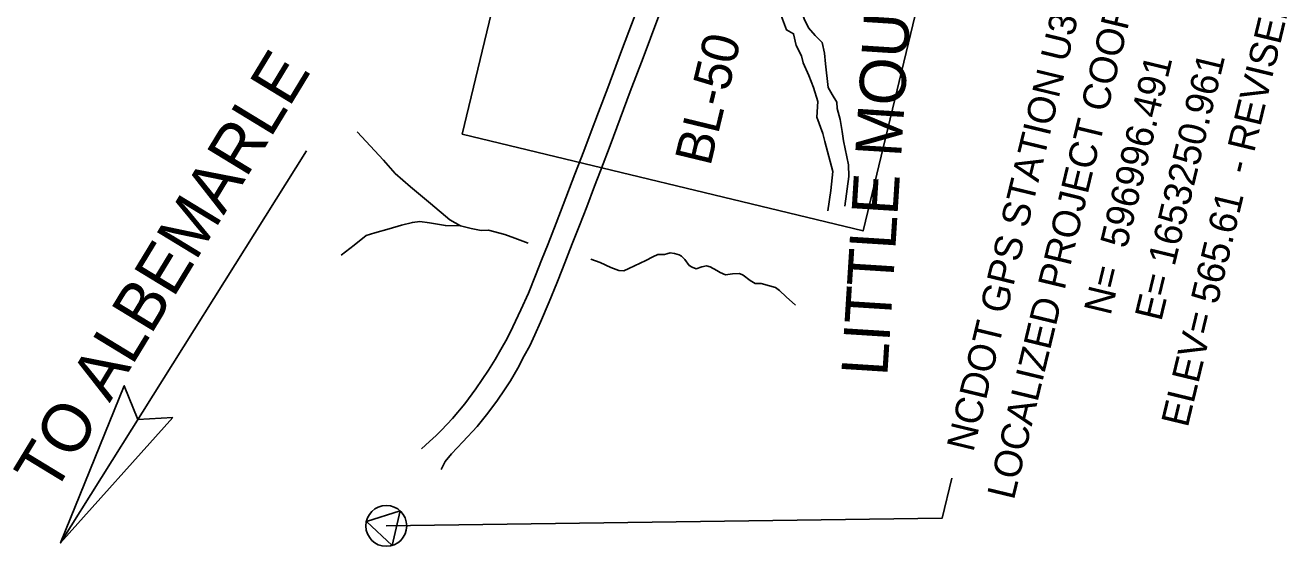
# Model space of a CAD drawing. Extents: x 1649669 to 1659218, y 588594 to 607900.
# Drawn here: x 1652859 to 1654231, y 596977 to 597539 of the extents above; entities that cross this region are included whole.
import ezdxf

# ---------------------------------------------------------------- set-up
doc = ezdxf.new("R2010")
doc.units = 0
for name, color, linetype in [('CTL NGS Horizontal CELL', 7, 'Continuous'), ('CTL NGS Horizontal Leader', 7, 'Continuous'), ('CTL NGS Horizontal Text', 7, 'Continuous'), ('CTL Supplemental Horizontal and Vertical Text', 7, 'Continuous'), ('Default', 7, 'Continuous'), ('Exist Hydro Jurisdictional Stream or Body of Water', 7, 'Continuous'), ('Exist Hydro Stream or Body of Water', 7, 'Continuous'), ('Exist Roads EOP', 7, 'Continuous'), ('Old_Level_20', 7, 'Continuous'), ('Prop Terminator CELL', 7, 'Continuous'), ('Sheet Cutting Line CELL', 7, 'Continuous'), ('Sheet Data Field CELL', 7, 'Continuous')]:
    doc.layers.add(name, color=color, linetype=linetype)

# ---------------------------------------------------------------- blocks, each defined once
blk = doc.blocks.new('CTL NGS HORIZONTAL')
at = {"layer": 'CTL NGS Horizontal CELL'}
blk.add_line((0, 0), (0, 0), dxfattribs=at)
blk.add_lwpolyline([(-0.0638, -0.0372), (0.0638, -0.0372), (0, 0.0737), (-0.0638, -0.0372)], dxfattribs=at)
blk.add_circle((0, 0), 0.0738, dxfattribs=at)

msp = doc.modelspace()

# ---------------------------------------------------------------- linework, layer by layer
at = {"layer": 'CTL NGS Horizontal Leader'}
msp.add_lwpolyline([(1653251, 596996.5), (1653854.1, 597004.8), (1653864.6, 597048.3)], dxfattribs=at)
at = {"layer": 'Default'}
msp.add_line((1652897.6, 596978), (1653164.4, 597403.3), dxfattribs=at)
at = {"layer": 'Exist Hydro Jurisdictional Stream or Body of Water'}
for points in [[(1653730.3, 597338.1), (1653733.3, 597360.2), (1653735.6, 597380.6), (1653726.8, 597413.4), (1653724.7, 597422.1), (1653718.3, 597439.8), (1653719.4, 597456.6), (1653714.6, 597471.9), (1653709.4, 597485), (1653703.2, 597498.6), (1653701.5, 597506), (1653695.8, 597517.3), (1653692.9, 597530.2), (1653685.3, 597534.3), (1653681, 597546), (1653677.2, 597556.7), (1653673.4, 597567.6)], [(1653748.4, 597343.1), (1653752.9, 597375.2), (1653752.5, 597388.1), (1653747.3, 597414.1), (1653745.8, 597424.3), (1653743.5, 597437.2), (1653740.3, 597449.2), (1653740, 597455.8), (1653734.8, 597464.4), (1653730.6, 597471.8), (1653727.7, 597497.5), (1653726.4, 597508.9), (1653723.9, 597520.6), (1653716.2, 597528.4), (1653709.3, 597536.5), (1653704.3, 597546.2), (1653699.9, 597559.6), (1653699.1, 597561), (1653693.8, 597570.3)]]:
    msp.add_lwpolyline(points, dxfattribs=at)
at = {"layer": 'Exist Hydro Stream or Body of Water'}
for points in [[(1653219.3, 597423.9), (1653248.1, 597393), (1653260.6, 597378.7), (1653277.4, 597364.2), (1653298.9, 597346), (1653319.9, 597328.5), (1653331.4, 597321.9), (1653343, 597319.1), (1653354.1, 597316.8), (1653361.8, 597317), (1653379.5, 597312.3), (1653390.4, 597308.4), (1653405.1, 597302.9)], [(1653202, 597289.9), (1653216.1, 597300.8), (1653229.1, 597311.4), (1653238.7, 597314.1), (1653254.1, 597318.7), (1653267.7, 597322.7), (1653279.3, 597325.6), (1653287.3, 597326.4), (1653297.8, 597325.1), (1653315.1, 597322.2), (1653331.4, 597321.9)], [(1653472.9, 597285.7), (1653483.2, 597282.2), (1653494.6, 597276.8), (1653503.3, 597273.3), (1653508.8, 597273.2), (1653514.2, 597275.5), (1653532.5, 597284.1), (1653540.1, 597288.4), (1653545.7, 597290.8), (1653548.1, 597290.8), (1653552.9, 597290.7), (1653555.3, 597291.6), (1653558.9, 597292.4), (1653563.8, 597291.9), (1653568.8, 597290.3), (1653571.2, 597288.9), (1653575.1, 597285.5), (1653579.7, 597278.8), (1653582.8, 597277.1), (1653587.2, 597275.4), (1653593.5, 597277.3), (1653598.5, 597278.4), (1653602.6, 597277.5), (1653609.6, 597273.4), (1653613.4, 597271.2), (1653619, 597268.6), (1653626.6, 597269.7), (1653634.2, 597270.1), (1653638.2, 597268.2), (1653645.7, 597262.4), (1653651.2, 597259.2), (1653657.9, 597259.4), (1653666.7, 597256.8), (1653673.2, 597255.1), (1653677.8, 597251.9), (1653684.8, 597244.9), (1653695.2, 597235.9)]]:
    msp.add_lwpolyline(points, dxfattribs=at)
at = {"layer": 'Exist Roads EOP'}
for points in [[(1653472.3, 597421.4), (1653481.4, 597445.1), (1653491.5, 597471.6), (1653506.4, 597511.5), (1653524.9, 597561.2), (1653542.1, 597605.7)], [(1653564.5, 597597.7), (1653558.4, 597580.8), (1653545.6, 597546.8), (1653529.7, 597504), (1653515.6, 597467.4), (1653493.8, 597408.8)], [(1653289.1, 597079.9), (1653297.9, 597087.9), (1653305.1, 597094.4), (1653310.9, 597100.2), (1653322.8, 597112.9), (1653336.1, 597128.7), (1653348.3, 597145), (1653361.9, 597165.4), (1653369.1, 597176.8), (1653375.4, 597187.7), (1653382.1, 597199.8), (1653388.4, 597212.3), (1653397.1, 597230.8), (1653405.2, 597249), (1653412.9, 597267.9), (1653419.6, 597284.5), (1653426.8, 597302.5), (1653435.3, 597324.6), (1653443, 597344.6), (1653455.7, 597377.8), (1653465.2, 597402.8), (1653472.3, 597421.4)], [(1653310.4, 597057.7), (1653315, 597066.3), (1653321.7, 597074.7), (1653334.1, 597087.6), (1653349.7, 597104.3), (1653361.3, 597118.6), (1653371.6, 597132.8), (1653379.3, 597144), (1653385.7, 597153.8), (1653393.7, 597167.6), (1653400.8, 597180.8), (1653406.7, 597191.8), (1653412.3, 597203.6), (1653418.4, 597217.4), (1653427.7, 597239.4), (1653436, 597259.7), (1653442.2, 597275.3), (1653452.8, 597302.3), (1653460.6, 597322.2), (1653468.5, 597342.4), (1653476.8, 597364.7), (1653483.4, 597381.6), (1653493.8, 597408.8)]]:
    msp.add_lwpolyline(points, dxfattribs=at)
at = {"layer": 'Prop Terminator CELL'}
msp.add_lwpolyline([(1653019.5, 597114), (1652897.6, 596978), (1652966.7, 597148.4), (1652981.6, 597111.9)], close=True, dxfattribs=at)
at = {"layer": 'Sheet Cutting Line CELL'}
msp.add_lwpolyline([(1653333.2, 597421.3), (1653600.8, 598529.7), (1654035.9, 598424.7), (1653768.3, 597316.3)], close=True, dxfattribs=at)

# ---------------------------------------------------------------- block references
at = {"layer": 'CTL NGS Horizontal CELL', "xscale": 300, "yscale": 300, "rotation": -42.96908576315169}
msp.add_blockref('CTL NGS HORIZONTAL', (1653251, 596996.5), dxfattribs=at)

# ---------------------------------------------------------------- texts
at = {"layer": 'CTL NGS Horizontal Text'}
for s, p in [('LOCALIZED PROJECT COORDINATES', (1653931.9, 597023.7)), ('NCDOT GPS STATION U3300B-1', (1653887.9, 597075.7)), ('ELEV= 565.61  - REVISED', (1654120.6, 597102.3)), ('N=  596996.491', (1654036.8, 597223.7)), ('E= 1653250.961', (1654091.9, 597217.4))]:
    msp.add_text(s, height=30, rotation=76.4261, dxfattribs=at).set_placement(p)
at = {"layer": 'CTL Supplemental Horizontal and Vertical Text'}
msp.add_text('BL-50', height=40, rotation=76.4261, dxfattribs=at).set_placement((1653602.6, 597385.6))
at = {"layer": 'Old_Level_20'}
msp.add_text('LITTLE MOUNTAIN CREEK', height=50, rotation=86.3815, dxfattribs=at).set_placement((1653794.6, 597158.1))
at = {"layer": 'Sheet Data Field CELL'}
msp.add_text('TO ALBEMARLE', height=52.501, rotation=58.686, dxfattribs=at).set_placement((1652890, 597029.4))

doc.saveas('drawing.dxf')
